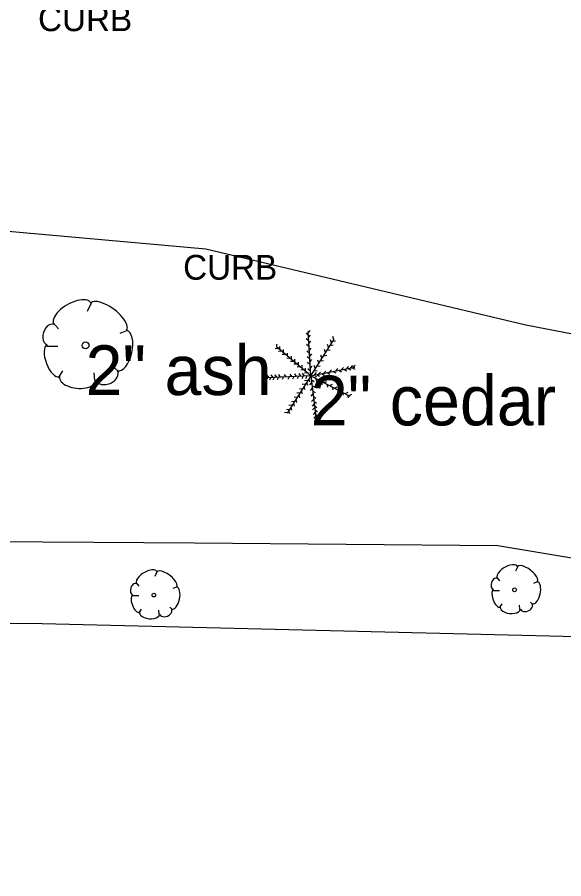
# Model space of a CAD drawing. Extents: x 1802180 to 1804859, y 572524 to 575172.
# Drawn here: x 1803395.8 to 1803450.8, y 574381.9 to 574468.6 of the extents above; entities that cross this region are included whole.
import ezdxf

# ---------------------------------------------------------------- set-up
doc = ezdxf.new("R2010")
doc.units = 0
for name, color, linetype in [('S_CURB_ANNOT', 7, 'Continuous'), ('S_DITCHLINE', 7, 'Continuous'), ('S_EDGE_PAVEMENT', 7, 'Continuous'), ('S_MISC_BOUNDARY', 7, 'Continuous'), ('S_TREE', 7, 'Continuous'), ('S_TREE_ANNOT', 7, 'Continuous')]:
    doc.layers.add(name, color=color, linetype=linetype)

msp = doc.modelspace()

# ---------------------------------------------------------------- linework, layer by layer
at = {"layer": 'S_DITCHLINE'}
msp.add_lwpolyline([(1803314.592, 574415.67), (1803331.72, 574415.749), (1803348.849, 574415.827), (1803365.978, 574415.905), (1803383.106, 574415.983), (1803398.38, 574415.857), (1803413.654, 574415.73), (1803428.929, 574415.604), (1803444.203, 574415.477), (1803462.697, 574412.372), (1803481.192, 574409.268), (1803496.936, 574404.044)], dxfattribs=at)
at = {"layer": 'S_EDGE_PAVEMENT'}
msp.add_lwpolyline([(1803334.544, 574446.409), (1803360.987, 574445.787), (1803392.251, 574447.343), (1803414.805, 574445.32), (1803447.003, 574437.693), (1803476.712, 574431.934), (1803495.533, 574427.575), (1803511.71, 574418.236)], dxfattribs=at)
at = {"layer": 'S_MISC_BOUNDARY'}
msp.add_lwpolyline([(1802879.237, 573886.73), (1803332.375, 573880.879), (1803406.037, 573888.598), (1803452.161, 573909.91), (1803480.862, 574044.753), (1803488.235, 574279.612), (1803486.641, 574405.443), (1803398.341, 574407.577), (1803194.958, 574408.853)], dxfattribs=at)
at = {"layer": 'S_TREE'}
for p, q in [((1803403.251, 574439.863), (1803402.863, 574439.01)), ((1803399.453, 574437.848), (1803399.957, 574437.266)), ((1803406.816, 574437.073), (1803406.157, 574436.801)), ((1803425.105, 574436.644), (1803424.881, 574436.843)), ((1803425.36, 574432.563), (1803425.092, 574436.999)), ((1803425.102, 574436.891), (1803425.291, 574437.124)), ((1803425.131, 574436.413), (1803425.32, 574436.647)), ((1803427.676, 574436.215), (1803427.587, 574436.501)), ((1803398.794, 574435.523), (1803399.918, 574435.523)), ((1803425.36, 574432.563), (1803421.896, 574435.473)), ((1803421.934, 574435.447), (1803421.934, 574435.747)), ((1803422.25, 574435.196), (1803422.25, 574435.496)), ((1803425.138, 574436.08), (1803424.913, 574436.278)), ((1803425.167, 574435.505), (1803424.942, 574435.704)), ((1803425.163, 574435.813), (1803425.352, 574436.047)), ((1803425.36, 574432.563), (1803427.702, 574436.247)), ((1803427.134, 574435.421), (1803427.045, 574435.708)), ((1803427.322, 574435.609), (1803427.618, 574435.653)), ((1803427.431, 574435.873), (1803427.342, 574436.16)), ((1803427.567, 574436.034), (1803427.863, 574436.078)), ((1803422.076, 574435.305), (1803421.779, 574435.265)), ((1803422.425, 574435.028), (1803422.126, 574435.004)), ((1803422.786, 574434.705), (1803422.487, 574434.681)), ((1803422.605, 574434.905), (1803422.605, 574435.205)), ((1803423.018, 574434.544), (1803423.018, 574434.844)), ((1803425.192, 574434.847), (1803424.968, 574435.046)), ((1803425.202, 574435.104), (1803425.391, 574435.337)), ((1803425.267, 574434.536), (1803425.455, 574434.769)), ((1803426.463, 574434.338), (1803426.374, 574434.624)), ((1803426.676, 574434.576), (1803426.973, 574434.62)), ((1803426.838, 574434.905), (1803426.748, 574435.192)), ((1803426.999, 574435.118), (1803427.296, 574435.162)), ((1803423.244, 574434.331), (1803422.945, 574434.307)), ((1803423.605, 574434.002), (1803423.306, 574433.978)), ((1803423.431, 574434.215), (1803423.431, 574434.515)), ((1803423.941, 574433.738), (1803423.642, 574433.713)), ((1803423.754, 574433.931), (1803423.754, 574434.231)), ((1803424.121, 574433.628), (1803424.121, 574433.928)), ((1803425.231, 574434.254), (1803425.007, 574434.453)), ((1803425.27, 574433.686), (1803425.045, 574433.885)), ((1803425.28, 574433.968), (1803425.468, 574434.202)), ((1803426.167, 574433.847), (1803426.077, 574434.134)), ((1803426.328, 574434.06), (1803426.625, 574434.104)), ((1803399.957, 574432.345), (1803400.422, 574433.043)), ((1803403.638, 574432.074), (1803403.561, 574432.849)), ((1803406.041, 574432.965), (1803405.576, 574433.391)), ((1803424.283, 574433.441), (1803423.984, 574433.417)), ((1803424.651, 574433.144), (1803424.352, 574433.12)), ((1803424.489, 574433.325), (1803424.489, 574433.625)), ((1803425.012, 574432.847), (1803424.713, 574432.823)), ((1803424.844, 574433.009), (1803424.844, 574433.309)), ((1803425.283, 574433.067), (1803425.058, 574433.266)), ((1803425.305, 574433.297), (1803425.494, 574433.531)), ((1803425.36, 574432.563), (1803429.781, 574433.43)), ((1803425.709, 574433.054), (1803426.005, 574433.098)), ((1803425.805, 574433.318), (1803425.716, 574433.605)), ((1803425.737, 574432.648), (1803425.938, 574432.87)), ((1803425.992, 574433.518), (1803426.289, 574433.562)), ((1803426.137, 574432.706), (1803426.338, 574432.928)), ((1803426.666, 574432.81), (1803426.868, 574433.032)), ((1803427.012, 574432.873), (1803427.265, 574432.713)), ((1803427.234, 574432.939), (1803427.435, 574433.161)), ((1803427.618, 574433.002), (1803427.872, 574432.842)), ((1803427.866, 574433.081), (1803428.068, 574433.303)), ((1803428.199, 574433.105), (1803428.452, 574432.945)), ((1803428.459, 574433.171), (1803428.661, 574433.393)), ((1803428.709, 574433.221), (1803428.962, 574433.061)), ((1803428.943, 574433.274), (1803429.145, 574433.496)), ((1803429.134, 574433.312), (1803429.388, 574433.151)), ((1803429.388, 574433.364), (1803429.59, 574433.586)), ((1803429.541, 574433.37), (1803429.794, 574433.209)), ((1803429.614, 574433.416), (1803429.816, 574433.638)), ((1803420.992, 574432.35), (1803420.858, 574432.082)), ((1803425.36, 574432.563), (1803420.908, 574432.351)), ((1803421.141, 574432.374), (1803420.973, 574432.622)), ((1803421.341, 574432.376), (1803421.207, 574432.108)), ((1803421.528, 574432.4), (1803421.36, 574432.648)), ((1803421.683, 574432.396), (1803421.549, 574432.127)), ((1803421.928, 574432.4), (1803421.76, 574432.648)), ((1803422.102, 574432.409), (1803421.968, 574432.14)), ((1803422.328, 574432.426), (1803422.16, 574432.674)), ((1803422.612, 574432.434), (1803422.478, 574432.166)), ((1803422.896, 574432.439), (1803422.728, 574432.687)), ((1803425.36, 574432.563), (1803422.98, 574428.789)), ((1803423.173, 574432.46), (1803423.039, 574432.192)), ((1803423.451, 574432.477), (1803423.282, 574432.726)), ((1803423.657, 574432.479), (1803423.523, 574432.211)), ((1803423.928, 574432.49), (1803423.76, 574432.738)), ((1803424.128, 574432.505), (1803423.994, 574432.237)), ((1803424.367, 574432.529), (1803424.199, 574432.777)), ((1803424.586, 574432.512), (1803424.452, 574432.243)), ((1803424.703, 574432.568), (1803424.534, 574432.816)), ((1803425.031, 574432.067), (1803424.733, 574432.033)), ((1803424.973, 574432.525), (1803424.839, 574432.256)), ((1803425.154, 574432.241), (1803425.229, 574431.95)), ((1803425.36, 574432.563), (1803429.276, 574430.518)), ((1803425.36, 574432.563), (1803425.891, 574428.191)), ((1803425.438, 574432.138), (1803425.694, 574431.982)), ((1803425.689, 574432.383), (1803425.955, 574432.523)), ((1803425.87, 574432.286), (1803425.941, 574431.994)), ((1803425.98, 574432.68), (1803426.233, 574432.519)), ((1803426.167, 574432.157), (1803426.432, 574432.297)), ((1803426.451, 574431.983), (1803426.521, 574431.691)), ((1803426.496, 574432.757), (1803426.749, 574432.596)), ((1803426.722, 574431.854), (1803426.987, 574431.994)), ((1803424.515, 574431.254), (1803424.217, 574431.22)), ((1803424.792, 574431.699), (1803424.494, 574431.665)), ((1803424.663, 574431.467), (1803424.739, 574431.176)), ((1803424.941, 574431.905), (1803425.017, 574431.615)), ((1803425.422, 574431.887), (1803425.226, 574431.66)), ((1803425.486, 574431.307), (1803425.29, 574431.08)), ((1803425.476, 574431.583), (1803425.733, 574431.427)), ((1803426.986, 574431.705), (1803427.057, 574431.414)), ((1803427.276, 574431.57), (1803427.542, 574431.71)), ((1803427.509, 574431.434), (1803427.58, 574431.143)), ((1803427.76, 574431.312), (1803428.026, 574431.452)), ((1803428.044, 574431.138), (1803428.115, 574430.846)), ((1803428.296, 574431.041), (1803428.561, 574431.181)), ((1803423.999, 574430.415), (1803423.701, 574430.381)), ((1803424.263, 574430.834), (1803423.965, 574430.801)), ((1803424.147, 574430.628), (1803424.223, 574430.338)), ((1803424.405, 574431.054), (1803424.481, 574430.763)), ((1803425.57, 574430.745), (1803425.374, 574430.518)), ((1803425.56, 574431.015), (1803425.816, 574430.859)), ((1803425.625, 574430.467), (1803425.881, 574430.311)), ((1803428.56, 574430.879), (1803428.631, 574430.588)), ((1803428.844, 574430.763), (1803429.109, 574430.903)), ((1803429.051, 574430.628), (1803429.121, 574430.336)), ((1803429.238, 574430.557), (1803429.503, 574430.697)), ((1803423.463, 574429.589), (1803423.165, 574429.555)), ((1803423.36, 574429.383), (1803423.436, 574429.092)), ((1803423.702, 574429.963), (1803423.404, 574429.93)), ((1803423.618, 574429.783), (1803423.694, 574429.492)), ((1803423.863, 574430.163), (1803423.939, 574429.873)), ((1803425.641, 574430.178), (1803425.445, 574429.951)), ((1803425.706, 574429.72), (1803425.51, 574429.492)), ((1803425.696, 574429.957), (1803425.952, 574429.801)), ((1803425.728, 574429.525), (1803425.984, 574429.369)), ((1803423.012, 574428.873), (1803422.714, 574428.839)), ((1803423.212, 574429.176), (1803422.914, 574429.142)), ((1803423.134, 574429.034), (1803423.21, 574428.744)), ((1803425.744, 574429.339), (1803425.548, 574429.112)), ((1803425.802, 574428.894), (1803425.606, 574428.667)), ((1803425.773, 574429.118), (1803426.029, 574428.962)), ((1803425.838, 574428.654), (1803426.094, 574428.498)), ((1803425.848, 574428.474), (1803425.652, 574428.247)), ((1803425.876, 574428.312), (1803426.133, 574428.156)), ((1803446.183, 574413.349), (1803445.969, 574412.879)), ((1803409.883, 574412.824), (1803409.669, 574412.354)), ((1803444.088, 574412.237), (1803444.366, 574411.917)), ((1803407.788, 574411.712), (1803408.066, 574411.392)), ((1803411.85, 574411.285), (1803411.486, 574411.135)), ((1803448.15, 574411.81), (1803447.787, 574411.66)), ((1803407.424, 574410.43), (1803408.044, 574410.43)), ((1803443.725, 574410.955), (1803444.345, 574410.955)), ((1803444.366, 574409.202), (1803444.623, 574409.587)), ((1803446.397, 574409.052), (1803446.354, 574409.48)), ((1803447.722, 574409.544), (1803447.466, 574409.779)), ((1803408.066, 574408.677), (1803408.322, 574409.061)), ((1803410.097, 574408.527), (1803410.054, 574408.955)), ((1803411.422, 574409.019), (1803411.166, 574409.254))]:
    msp.add_line(p, q, dxfattribs=at)
for centre, radius in [((1803402.693, 574435.617), 0.341), ((1803445.875, 574411.007), 0.188), ((1803409.575, 574410.482), 0.188)]:
    msp.add_circle(centre, radius, dxfattribs=at)
for centre, major_axis, ratio, start_param, end_param in [((1803401.356, 574438.819), (1.857, 1.085), 0.471018, 0, 3.141593), ((1803405.011, 574438.496), (-1.813, 1.36), 0.405113, 3.141593, 6.283186), ((1803399.122, 574436.705), (0.305, 1.027), 0.646762, 0, 3.141593), ((1803406.366, 574435.087), (0.458, 2.04), 0.482994, 3.141593, 6.283185), ((1803399.427, 574434.054), (-0.611, 1.596), 0.420543, 6.283185, 9.424777), ((1803404.845, 574432.566), (1.092, 0.462), 0.711534, 3.141592, 6.283185), ((1803401.888, 574432.274), (-1.832, 0.194), 0.529943, 0, 3.141593), ((1803408.838, 574412.249), (1.024, 0.598), 0.471018, 0, 3.141593), ((1803410.854, 574412.07), (-1, 0.75), 0.405113, 3.141593, 6.283186), ((1803445.138, 574412.774), (1.024, 0.598), 0.471018, 0, 3.141593), ((1803447.154, 574412.595), (-1, 0.75), 0.405113, 3.141593, 6.283186), ((1803443.905, 574411.607), (0.168, 0.567), 0.646762, 0, 3.141593), ((1803407.605, 574411.082), (0.168, 0.567), 0.646762, 0, 3.141593), ((1803411.602, 574410.189), (0.253, 1.125), 0.482994, 3.141593, 6.283185), ((1803447.902, 574410.714), (0.253, 1.125), 0.482994, 3.141593, 6.283185), ((1803407.773, 574409.62), (-0.337, 0.88), 0.420543, 6.283185, 9.424777), ((1803444.074, 574410.145), (-0.337, 0.88), 0.420543, 6.283185, 9.424777), ((1803447.063, 574409.324), (0.602, 0.255), 0.711534, 3.141592, 6.283185), ((1803409.131, 574408.637), (-1.01, 0.107), 0.529943, 0, 3.141593), ((1803410.762, 574408.799), (0.602, 0.255), 0.711534, 3.141592, 6.283185), ((1803445.431, 574409.162), (-1.01, 0.107), 0.529943, 0, 3.141593)]:
    msp.add_ellipse(centre, major_axis=major_axis, ratio=ratio, start_param=start_param, end_param=end_param, dxfattribs=at)

# ---------------------------------------------------------------- texts
at = {"layer": 'S_CURB_ANNOT'}
for p in [(1803397.911, 574467.241), (1803412.513, 574442.225)]:
    msp.add_text('CURB', height=2.5, dxfattribs=at).set_placement(p)
at = {"layer": 'S_TREE_ANNOT'}
for s, p in [('2" ash ', (1803402.693, 574430.617)), ('2" cedar ', (1803425.36, 574427.563))]:
    msp.add_text(s, height=5, dxfattribs=at).set_placement(p)

doc.saveas('drawing.dxf')
